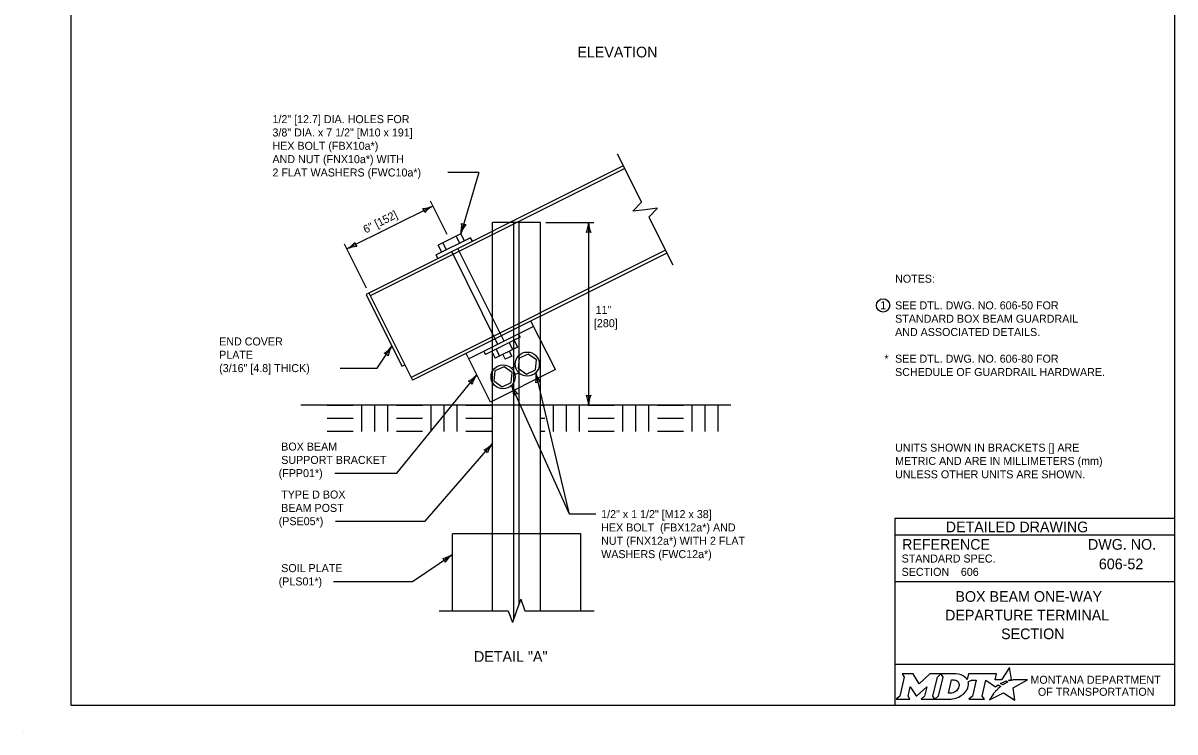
# Model space of a CAD drawing. Extents: x 49991.4 to 50021, y 49987.6 to 50011.4.
# Drawn here: x 49999.98 to 50008.61, y 49999.86 to 50005.18 of the extents above; entities that cross this region are included whole.
import ezdxf

# ---------------------------------------------------------------- set-up
doc = ezdxf.new("R2010")
doc.units = 0
for name, color, linetype in [('Level 1', 7, 'Continuous'), ('Level 2', 7, 'Continuous'), ('Level 3', 7, 'Continuous'), ('Level 4', 7, 'Continuous'), ('Level 6', 7, 'Continuous')]:
    doc.layers.add(name, color=color, linetype=linetype)

msp = doc.modelspace()

# ---------------------------------------------------------------- linework, layer by layer
at = {"layer": 'Level 1'}
for p, q in [((50004.4777, 50004.108), (50002.5486, 50003.1434)), ((50003.6289, 50003.6836), (50003.4966, 50003.6836)), ((50003.4966, 50003.6174), (50003.4966, 50003.6836)), ((50003.3327, 50003.569), (50003.0735, 50003.4393)), ((50003.2594, 50003.5984), (50003.0901, 50003.5137)), ((50003.2513, 50003.5282), (50003.2248, 50003.5811)), ((50003.2858, 50003.5455), (50003.2594, 50003.5984)), ((50003.3461, 50003.5422), (50003.3327, 50003.569)), ((50003.1165, 50003.4608), (50003.0901, 50003.5137)), ((50003.1511, 50003.4781), (50003.1246, 50003.531)), ((50004.8048, 50003.4536), (50002.8973, 50002.4999)), ((50003.0869, 50003.4126), (50003.0735, 50003.4393)), ((50002.5486, 50003.1434), (50002.8176, 50002.6053)), ((50002.5701, 50003.1542), (50002.8973, 50002.4999)), ((50003.8575, 50002.7988), (50003.8575, 50002.98)), ((50003.8049, 50002.9026), (50003.3197, 50002.66)), ((50003.9684, 50002.58), (50003.7843, 50002.9434)), ((50003.7034, 50002.8229), (50003.4441, 50002.6933)), ((50003.6844, 50002.7485), (50003.5169, 50002.6648)), ((50003.4824, 50002.3345), (50003.2992, 50002.7009)), ((50002.8176, 50002.6053), (50002.8392, 50002.6161)), ((50003.9684, 50002.58), (50003.4824, 50002.3345)), ((50003.6688, 50002.6065), (50003.6391, 50002.5902)), ((50003.6953, 50002.5561), (50003.6651, 50002.5411)), ((50003.8575, 50002.312), (50003.8575, 50002.524)), ((50005.2849, 50002.312), (50002.0592, 50002.312)), ((50002.4518, 50002.3097), (50002.2569, 50002.3097)), ((50002.5168, 50002.1148), (50002.5168, 50002.3097)), ((50002.6143, 50002.1148), (50002.6143, 50002.3097)), ((50002.712, 50002.1148), (50002.712, 50002.3097)), ((50002.9719, 50002.3097), (50002.777, 50002.3097)), ((50003.0369, 50002.1148), (50003.0369, 50002.3097)), ((50003.1344, 50002.1148), (50003.1344, 50002.3097)), ((50003.2318, 50002.1148), (50003.2318, 50002.3097)), ((50003.492, 50002.3097), (50003.2971, 50002.3097)), ((50003.4966, 50002.312), (50003.4966, 50002.3417)), ((50003.9552, 50002.1148), (50003.9552, 50002.3097)), ((50004.0526, 50002.1148), (50004.0526, 50002.3097)), ((50004.15, 50002.1148), (50004.15, 50002.3097)), ((50004.4102, 50002.3097), (50004.2151, 50002.3097)), ((50004.4752, 50002.1148), (50004.4752, 50002.3097)), ((50004.5727, 50002.1148), (50004.5727, 50002.3097)), ((50004.6701, 50002.1148), (50004.6701, 50002.3097)), ((50004.9303, 50002.3097), (50004.7352, 50002.3097)), ((50004.9953, 50002.1148), (50004.9953, 50002.3097)), ((50005.0928, 50002.1148), (50005.0928, 50002.3097)), ((50005.1902, 50002.1148), (50005.1902, 50002.3097)), ((50002.4518, 50002.2123), (50002.2569, 50002.2123)), ((50002.9719, 50002.2123), (50002.777, 50002.2123)), ((50003.492, 50002.2123), (50003.2971, 50002.2123)), ((50004.4102, 50002.2123), (50004.2151, 50002.2123)), ((50004.9303, 50002.2123), (50004.7352, 50002.2123)), ((50002.4518, 50002.1148), (50002.2569, 50002.1148)), ((50002.9719, 50002.1148), (50002.777, 50002.1148)), ((50003.492, 50002.1148), (50003.2971, 50002.1148)), ((50004.4102, 50002.1148), (50004.2151, 50002.1148)), ((50004.9303, 50002.1148), (50004.7352, 50002.1148)), ((49999.9766, 49999.8624), (49999.9766, 49999.8624))]:
    msp.add_line(p, q, dxfattribs=at)
for points in [[(50008.6146, 50011.2628), (50000.3356, 50011.2628), (50000.3356, 50000.0624), (50008.6146, 50000.0624)], [(50003.8264, 50002.6528), (50003.7652, 50002.6964), (50003.6968, 50002.6651), (50003.6896, 50002.5903), (50003.7509, 50002.5467), (50003.8193, 50002.5779)], [(50003.6448, 50002.557), (50003.5836, 50002.6006), (50003.5152, 50002.5694), (50003.508, 50002.4945), (50003.5693, 50002.4509), (50003.6377, 50002.4822)]]:
    msp.add_lwpolyline(points, close=True, dxfattribs=at)
for points in [[(50003.6586, 50002.8005), (50003.6844, 50002.7485)], [(50003.6918, 50002.846), (50003.7034, 50002.8229)], [(50003.4326, 50002.7164), (50003.4441, 50002.6933)], [(50003.491, 50002.7167), (50003.5169, 50002.6648)], [(50003.5238, 50002.7331), (50003.5497, 50002.6811)], [(50003.6219, 50002.7821), (50003.6479, 50002.7303)], [(50003.6228, 50002.7177), (50003.6412, 50002.6811)], [(50003.5747, 50002.6937), (50003.593, 50002.657)], [(50003.6412, 50002.6811), (50003.593, 50002.657)], [(50003.8901, 50002.3097), (50003.8635, 50002.3097)], [(50003.8901, 50002.2123), (50003.8577, 50002.2123)], [(50003.8901, 50002.1148), (50003.8577, 50002.1148)]]:
    msp.add_lwpolyline(points, dxfattribs=at)
for centre in [(50003.7579, 50002.6212), (50003.5762, 50002.5254)]:
    msp.add_circle(centre, 0.0902, dxfattribs=at)
at = {"layer": 'Level 2'}
for p, q in [((50008.6146, 50001.4624), (50006.5146, 50001.4624)), ((50006.5146, 50001.4624), (50006.5146, 50000.0624)), ((50008.6146, 50001.3374), (50006.5146, 50001.3374)), ((50008.2507, 50001.1223), (50008.2507, 50001.1223)), ((50008.6146, 50000.9874), (50006.5146, 50000.9874)), ((50007.0089, 50001.0629), (50007.0089, 50001.0629)), ((50007.5646, 50000.7383), (50007.5646, 50000.7383)), ((50008.6146, 50000.3693), (50006.5146, 50000.3693))]:
    msp.add_line(p, q, dxfattribs=at)
for points in [[(50006.5701, 50000.2974), (50006.5842, 50000.274), (50006.5507, 50000.1307), (50006.525, 50000.1082), (50006.6266, 50000.1082), (50006.6131, 50000.131), (50006.6293, 50000.2011), (50006.673, 50000.1321), (50006.6783, 50000.1321), (50006.7534, 50000.2016), (50006.737, 50000.1305), (50006.7123, 50000.1085), (50006.8139, 50000.1085), (50006.8001, 50000.1318), (50006.8333, 50000.2742)], [(50006.8333, 50000.2742), (50006.8586, 50000.2974), (50006.7762, 50000.2974), (50006.6966, 50000.2244), (50006.6521, 50000.2971), (50006.5701, 50000.2974)], [(50006.9722, 50000.2974), (50006.8586, 50000.2974), (50006.8733, 50000.2745), (50006.8394, 50000.1307), (50006.8139, 50000.1085), (50006.9245, 50000.1085)], [(50007.3771, 50000.2447), (50007.3668, 50000.2503), (50007.3784, 50000.2531), (50007.39, 50000.2551), (50007.3726, 50000.3452), (50007.3131, 50000.2539), (50007.2658, 50000.2532), (50007.2761, 50000.2973), (50007.0669, 50000.2974), (50007.0568, 50000.2549), (50007.051, 50000.2632)], [(50006.9962, 50000.2107), (50006.995, 50000.2026), (50006.9918, 50000.1933), (50006.9876, 50000.1851), (50006.982, 50000.1776), (50006.9755, 50000.1707), (50006.9676, 50000.1644), (50006.9593, 50000.1597), (50006.9502, 50000.1558), (50006.9411, 50000.1535), (50006.9319, 50000.1526), (50006.916, 50000.1526), (50006.9396, 50000.2526), (50006.9556, 50000.2526), (50006.9632, 50000.252), (50006.9708, 50000.2501), (50006.9774, 50000.2471), (50006.9835, 50000.2429), (50006.9883, 50000.2379), (50006.992, 50000.2319), (50006.9947, 50000.2257), (50006.9963, 50000.2183), (50006.9963, 50000.2153), (50006.9962, 50000.2107)], [(50007.0636, 50000.2383), (50007.0882, 50000.2514), (50007.1251, 50000.2514), (50007.0965, 50000.1309), (50007.069, 50000.1082), (50007.1852, 50000.1082), (50007.1682, 50000.1311), (50007.1964, 50000.2513), (50007.2677, 50000.1996), (50007.2888, 50000.2147), (50007.3085, 50000.2038)], [(50007.2527, 50000.1479), (50007.2374, 50000.1235), (50007.2327, 50000.116), (50007.2269, 50000.1074), (50007.2246, 50000.1031), (50007.3299, 50000.1562), (50007.4138, 50000.1011), (50007.4007, 50000.1938), (50007.5076, 50000.2522), (50007.4583, 50000.253), (50007.4282, 50000.2534), (50007.4074, 50000.2537), (50007.4006, 50000.2522), (50007.3957, 50000.251), (50007.3873, 50000.2487), (50007.3771, 50000.2447)], [(50007.3267, 50000.2171), (50007.3243, 50000.2154), (50007.306, 50000.225), (50007.3163, 50000.2307), (50007.3204, 50000.2329), (50007.329, 50000.2369), (50007.3347, 50000.2395), (50007.3426, 50000.2425), (50007.3499, 50000.2452), (50007.3617, 50000.2378), (50007.3577, 50000.2357), (50007.3531, 50000.2332), (50007.3489, 50000.231), (50007.3439, 50000.2281), (50007.342, 50000.227), (50007.3393, 50000.2254), (50007.3368, 50000.224), (50007.3345, 50000.2224), (50007.3319, 50000.2206), (50007.3292, 50000.2188), (50007.3267, 50000.2171)], [(50006.9702, 50000.1158), (50006.9786, 50000.1184), (50006.9916, 50000.1238), (50007.012, 50000.1348)], [(50007.2666, 50000.164), (50007.2666, 50000.164)]]:
    msp.add_lwpolyline(points, dxfattribs=at)
msp.add_circle((50006.4259, 50003.0613), 0.05, dxfattribs=at)
for centre, radius, start, end in [((50006.9953, 50000.219), 0.0709, 339.53292, 15.85821), ((50006.9513, 50000.2363), 0.1183, 300.91025, 339.13831)]:
    msp.add_arc(centre, radius, start, end, dxfattribs=at)
for centre, major_axis, ratio, start_param, end_param in [((50006.9701, 50000.25), (0.0834, -0.0037), 0.568097, 0.61298, 1.570796), ((50007.0257, 50000.2573), (0.0361, -0.0295), 0.469099, 1.225588, 1.570796), ((50007.2974, 50000.1941), (-0.0112, -0.0097), 0.021651, 3.157348, 6.283185), ((50006.9248, 50000.2568), (0, 0.1484), 0.987302, 3.139398, 3.456847), ((50007.2597, 50000.1559), (-0.00694, -0.00806), 0.008222, 0, 3.137361), ((50007.2764, 50000.1742), (-0.0098, -0.0102), 0.016458, 3.141593, 6.279097)]:
    msp.add_ellipse(centre, major_axis=major_axis, ratio=ratio, start_param=start_param, end_param=end_param, dxfattribs=at)
at = {"layer": 'Level 3'}
for p, q in [((50003.3937, 50004.0579), (50003.1621, 50004.0579)), ((50003.1568, 50003.5918), (50003.0316, 50003.8423)), ((50003.0495, 50003.8065), (50002.4051, 50003.4843)), ((50003.8975, 50003.6836), (50004.2575, 50003.6836)), ((50004.2175, 50003.6836), (50004.2175, 50002.312)), ((50002.5522, 50003.1899), (50002.3872, 50003.5201)), ((50002.6309, 50002.5909), (50002.7424, 50002.7558)), ((50002.3556, 50002.5909), (50002.6309, 50002.5909)), ((50004.0747, 50001.496), (50003.8217, 50002.5574)), ((50004.0747, 50001.496), (50003.64, 50002.4616)), ((50002.9928, 50001.443), (50003.4966, 50002.0248)), ((50002.3139, 50001.8035), (50002.7795, 50001.8035)), ((50004.272, 50001.496), (50004.0747, 50001.496)), ((50002.3196, 50001.443), (50002.9928, 50001.443)), ((50002.8965, 50000.9911), (50003.1958, 50001.1929)), ((50002.3058, 50000.9911), (50002.8965, 50000.9911))]:
    msp.add_line(p, q, dxfattribs=at)
for points in [[(50003.3937, 50004.0579), (50003.2594, 50003.5984)], [(50002.7795, 50001.8035), (50003.3792, 50002.5409)]]:
    msp.add_lwpolyline(points, dxfattribs=at)
for centre, radius, start, end in [((50002.9557, 50004.0198), 0.233, 274.48789, 293.73774), ((50002.9348, 50003.7492), 0.0548, 8.70387, 44.42623), ((50003.157, 50003.6119), 0.2223, 118.92553, 139.10904), ((50003.0436, 50003.6519), 0.2223, 346.06791, 6.25142), ((50003.4795, 50003.5221), 0.233, 141.63027, 160.88012), ((50003.2953, 50003.7214), 0.0548, 235.84625, 271.56861), ((50003.9848, 50003.6951), 0.233, 337.92284, 357.17269), ((50004.4396, 50003.6927), 0.2223, 182.36048, 202.54399), ((50004.2175, 50003.5553), 0.0548, 72.13882, 107.86118), ((50002.2975, 50003.6789), 0.2223, 298.92553, 319.10904), ((50002.4989, 50003.271), 0.233, 94.48789, 113.73774), ((50002.5198, 50003.5416), 0.0548, 188.70387, 224.42623), ((50002.5635, 50002.8878), 0.2223, 303.3952, 323.57871), ((50002.9416, 50002.635), 0.233, 148.7665, 168.01635), ((50002.6706, 50002.6496), 0.0548, 38.07801, 73.80037), ((50003.2059, 50002.6966), 0.233, 298.80177, 318.05162), ((50003.5573, 50002.4078), 0.2223, 143.23941, 163.42292), ((50004.0356, 50002.6178), 0.2223, 195.76918, 215.95269), ((50003.5926, 50002.5146), 0.233, 351.33154, 10.58139), ((50003.2983, 50002.4414), 0.0548, 33.01775, 68.74011), ((50003.8388, 50002.5612), 0.2223, 206.59368, 226.77719), ((50003.4231, 50002.3766), 0.233, 2.15604, 21.40589), ((50003.8514, 50002.4327), 0.0548, 85.54752, 121.26988), ((50003.6927, 50002.3447), 0.0548, 96.37202, 132.09438), ((50003.9954, 50002.3028), 0.2223, 2.36048, 22.54399), ((50004.2175, 50002.4402), 0.0548, 252.13882, 287.86118), ((50004.4502, 50002.3005), 0.233, 157.92284, 177.17269), ((50003.3282, 50002.1858), 0.233, 297.03327, 316.28312), ((50003.6705, 50001.8863), 0.2223, 141.47091, 161.65442), ((50003.4126, 50001.9278), 0.0548, 31.24925, 66.97161), ((50003.0752, 50001.3923), 0.233, 281.91942, 301.16927), ((50003.0895, 50001.1213), 0.0548, 16.1354, 51.85776), ((50003.3276, 50001.0139), 0.2223, 126.35706, 146.54057)]:
    msp.add_arc(centre, radius, start, end, dxfattribs=at)
at = {"layer": 'Level 4'}
for p, q in [((50004.4881, 50004.0873), (50002.5805, 50003.1335)), ((50003.8575, 50003.6836), (50003.6289, 50003.6836)), ((50003.6566, 50000.7128), (50003.6566, 50003.6836)), ((50003.6975, 50000.8282), (50003.6975, 50003.6836)), ((50003.8575, 50002.98), (50003.8575, 50003.6836)), ((50003.4966, 50002.3417), (50003.4966, 50003.6174)), ((50003.5853, 50002.7928), (50003.2377, 50003.488)), ((50004.7945, 50003.4743), (50002.8869, 50002.5205)), ((50003.5375, 50002.7689), (50003.1928, 50003.4655)), ((50003.8575, 50002.524), (50003.8575, 50002.7988)), ((50003.4966, 50000.7709), (50003.4966, 50002.312)), ((50003.8575, 50000.771), (50003.8575, 50002.312)), ((50004.1583, 50001.3494), (50003.1958, 50001.3494)), ((50003.1958, 50000.7708), (50003.1958, 50001.3494)), ((50004.1583, 50000.7711), (50004.1583, 50001.3494))]:
    msp.add_line(p, q, dxfattribs=at)
at = {"layer": 'Level 6'}
for p, q in [((50004.433, 50004.1974), (50004.6144, 50003.8344)), ((50004.6144, 50003.8344), (50004.5499, 50003.7675)), ((50004.6422, 50003.7789), (50004.5499, 50003.7675)), ((50004.7345, 50003.7903), (50004.6422, 50003.7789)), ((50004.7345, 50003.7903), (50004.67, 50003.7232)), ((50004.67, 50003.7232), (50004.8495, 50003.3642)), ((50003.7083, 50000.8587), (50003.6772, 50000.771)), ((50003.7083, 50000.8587), (50003.7394, 50000.771)), ((50003.0958, 50000.7708), (50003.615, 50000.7709)), ((50003.615, 50000.7709), (50003.6461, 50000.6833)), ((50003.6772, 50000.771), (50003.6461, 50000.6833)), ((50003.7394, 50000.771), (50004.2583, 50000.7711))]:
    msp.add_line(p, q, dxfattribs=at)

# ---------------------------------------------------------------- texts
at = {"layer": 'Level 2'}
for s, height, p in [('ELEVATION', 0.08, (50004.1336, 50004.9207)), ('1/2" [12.7] DIA. HOLES FOR  ', 0.06, (50001.8471, 50004.4279)), ('3/8" DIA. x 7 1/2" [M10 x 191] ', 0.06, (50001.8471, 50004.3279)), ('HEX BOLT (FBX10a*)', 0.06, (50001.8471, 50004.2279)), ('AND NUT (FNX10a*) WITH', 0.06, (50001.8471, 50004.1279)), ('2 FLAT WASHERS (FWC10a*)', 0.06, (50001.8471, 50004.0279)), ('NOTES:', 0.06, (50006.516, 50003.2314)), ('11"', 0.06, (50004.2698, 50002.9978)), ('1', 0.06, (50006.4043, 50003.0316)), ('SEE DTL. DWG. NO. 606-50 FOR', 0.06, (50006.516, 50003.0314)), ('STANDARD BOX BEAM GUARDRAIL ', 0.06, (50006.516, 50002.9314)), ('[280]', 0.06, (50004.2575, 50002.8978)), ('AND ASSOCIATED DETAILS.', 0.06, (50006.516, 50002.8314)), ('END COVER', 0.06, (50001.4473, 50002.7609)), ('PLATE', 0.06, (50001.4473, 50002.6609)), ('(3/16" [4.8] THICK)', 0.06, (50001.4473, 50002.5609)), ('*', 0.06, (50006.4363, 50002.6314)), ('SEE DTL. DWG. NO. 606-80 FOR', 0.06, (50006.516, 50002.6314)), ('SCHEDULE OF GUARDRAIL HARDWARE.', 0.06, (50006.516, 50002.5314)), ('BOX BEAM', 0.06, (50001.9126, 50001.9724)), ('UNITS SHOWN IN BRACKETS [] ARE ', 0.06, (50006.516, 50001.9646)), ('SUPPORT BRACKET', 0.06, (50001.9126, 50001.8724)), ('METRIC AND ARE IN MILLIMETERS (mm) ', 0.06, (50006.516, 50001.8646)), ('(FPP01*)', 0.06, (50001.8936, 50001.7735)), ('UNLESS OTHER UNITS ARE SHOWN.', 0.06, (50006.516, 50001.7646)), ('TYPE D BOX', 0.06, (50001.9126, 50001.6129)), ('BEAM POST', 0.06, (50001.9126, 50001.5126)), ('1/2" x 1 1/2" [M12 x 38]', 0.06, (50004.312, 50001.466)), ('(PSE05*)', 0.06, (50001.8939, 50001.413)), ('HEX BOLT  (FBX12a*) AND ', 0.06, (50004.312, 50001.366)), ('DETAILED DRAWING', 0.0799, (50006.8956, 50001.3599)), ('NUT (FNX12a*) WITH 2 FLAT ', 0.06, (50004.312, 50001.266)), ('REFERENCE', 0.08, (50006.5682, 50001.229)), ('DWG. NO.', 0.08, (50007.9624, 50001.229)), ('WASHERS (FWC12a*) ', 0.06, (50004.312, 50001.166)), ('STANDARD SPEC.', 0.06, (50006.5649, 50001.133)), ('606-52', 0.08, (50008.044, 50001.0823)), ('SOIL PLATE', 0.06, (50001.9126, 50001.0612)), ('SECTION', 0.06, (50006.5649, 50001.033)), ('606', 0.06, (50007.0089, 50001.0329)), ('(PLS01*)', 0.06, (50001.8937, 50000.9611)), ('BOX BEAM ONE-WAY', 0.08, (50006.9683, 50000.8383)), ('DEPARTURE TERMINAL', 0.08, (50006.8908, 50000.6983)), ('SECTION', 0.08, (50007.311, 50000.5583)), ('DETAIL "A"', 0.08, (50003.3582, 50000.3883)), ('MONTANA DEPARTMENT', 0.06, (50007.5308, 50000.2236)), ('OF TRANSPORTATION', 0.06, (50007.587, 50000.1336))]:
    msp.add_text(s, height=height, dxfattribs=at).set_placement(p)
msp.add_text('6" [152]', height=0.06, rotation=26.56505, dxfattribs=at).set_placement((50002.546, 50003.5994))

doc.saveas('drawing.dxf')
